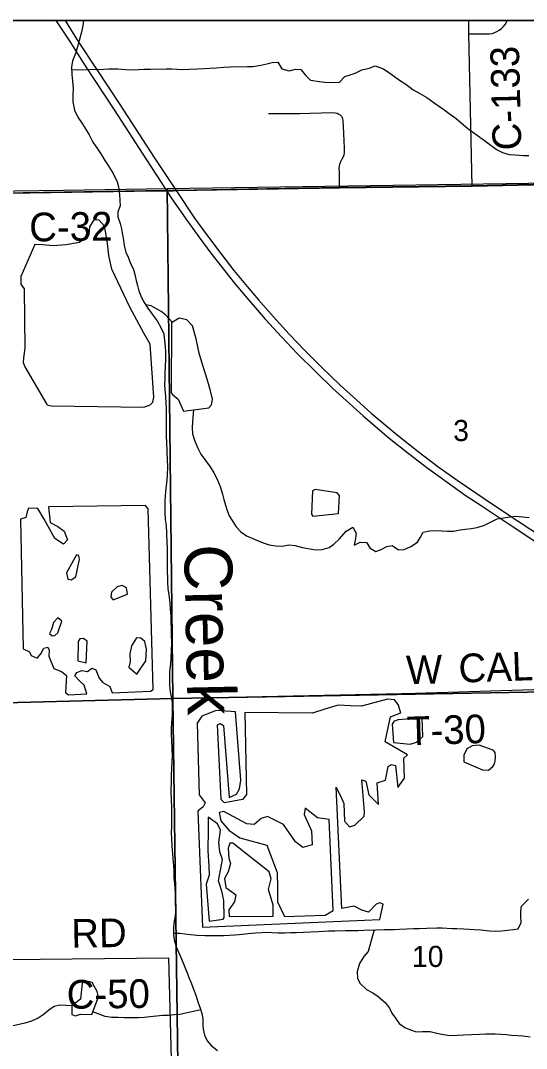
# Model space of a CAD drawing. Extents: x 0 to 36.9, y 0 to 22.
# Drawn here: x 6.858 to 7.859, y 18.864 to 20.9 of the extents above; entities that cross this region are included whole.
import ezdxf

# ---------------------------------------------------------------- set-up
doc = ezdxf.new("R2010")
doc.units = 0
for name, color, linetype in [('GM_X_County_Road', 7, 'Continuous'), ('GM_X_County_Road_Text', 7, 'Continuous'), ('GM_X_Interstate_Route', 7, 'Continuous'), ('GM_X_Major_River', 7, 'Continuous'), ('GM_X_Major_River_Text', 7, 'Continuous'), ('GM_X_Minor_Lake', 7, 'Continuous'), ('GM_X_Minor_River', 7, 'Continuous'), ('GM_X_Rail_Line', 7, 'Continuous'), ('GM_X_Section', 7, 'Continuous'), ('GM_X_Section_Text', 7, 'Continuous'), ('GM_X_Township_Road', 7, 'Continuous'), ('GM_X_Township_Road_Text', 7, 'Continuous'), ('SH_Cut_Line', 7, 'Continuous'), ('SH_Data', 7, 'Continuous')]:
    doc.layers.add(name, color=color, linetype=linetype)

msp = doc.modelspace()

# ---------------------------------------------------------------- linework, layer by layer
at = {"layer": 'GM_X_County_Road'}
for p, q in [((7.1241, 20.5624), (7.141, 20.5627)), ((7.1903, 17.5251), (7.1513, 19.0425))]:
    msp.add_line(p, q, dxfattribs=at)
for points in [[(7.7516, 20.5719), (7.7455, 20.8734), (7.745, 20.9)], [(7.1599, 20.563), (7.1658, 20.5631), (7.4891, 20.5688), (7.7516, 20.5719)], [(7.7516, 20.5719), (8.1453, 20.5805), (8.4791, 20.5838)], [(6.1629, 20.5471), (6.1729, 20.5473), (7.1241, 20.5624)], [(7.141, 20.5627), (7.147, 20.5628), (7.1599, 20.563)], [(7.1513, 19.0425), (6.3225, 19.0341), (5.5744, 19.0226)]]:
    msp.add_lwpolyline(points, dxfattribs=at)
at = {"layer": 'GM_X_Interstate_Route'}
for points in [[(6.9276, 20.9), (6.955, 20.8582), (6.9859, 20.8105), (7.043, 20.7231), (7.1073, 20.6241), (7.1371, 20.5785), (7.147, 20.5628), (7.1487, 20.5602)], [(6.9458, 20.9), (6.9706, 20.8604), (7.0082, 20.804), (7.054, 20.7339), (7.1224, 20.6287), (7.1658, 20.5631)], [(7.1487, 20.5602), (7.1557, 20.5489), (7.185, 20.5072), (7.2106, 20.4716), (7.2347, 20.4391), (7.2567, 20.4109), (7.2809, 20.3805), (7.3094, 20.3463), (7.3426, 20.3081), (7.3741, 20.2735), (7.4057, 20.2402), (7.4428, 20.2033), (7.4757, 20.1713), (7.5023, 20.1471), (7.5362, 20.1167), (7.5876, 20.0729), (7.6281, 20.0409), (7.6647, 20.0124), (7.7026, 19.9854), (7.7381, 19.9599), (7.7694, 19.9392), (7.8251, 19.9023), (7.8759, 19.8687)], [(7.1658, 20.5631), (7.2018, 20.5089), (7.2259, 20.4763), (7.2543, 20.4387), (7.2801, 20.4051), (7.3063, 20.3732), (7.329, 20.3467), (7.3588, 20.3133), (7.3894, 20.2789), (7.4211, 20.246), (7.4535, 20.2135), (7.4905, 20.1778), (7.5234, 20.1482), (7.5522, 20.1225), (7.6035, 20.0797), (7.6447, 20.0464), (7.684, 20.0167), (7.722, 19.9893), (7.759, 19.9643), (7.7901, 19.9432), (7.8431, 19.9082), (7.8929, 19.8754)]]:
    msp.add_lwpolyline(points, dxfattribs=at)
at = {"layer": 'GM_X_Major_River'}
for points in [[(6.9824, 20.9), (6.9811, 20.89), (6.9787, 20.8767), (6.974, 20.8607), (6.9708, 20.8477), (6.9661, 20.8328), (6.9603, 20.8202), (6.9586, 20.8076), (6.9593, 20.7932), (6.9606, 20.7799), (6.9617, 20.7652), (6.9615, 20.7534), (6.961, 20.739), (6.9643, 20.7223), (6.9714, 20.7088), (6.9796, 20.696), (6.9866, 20.6855), (6.9933, 20.6735), (7.0011, 20.6592), (7.0101, 20.6457), (7.0183, 20.6341), (7.0246, 20.6225), (7.0312, 20.6127), (7.0414, 20.5969), (7.0489, 20.5808), (7.0517, 20.5706), (7.0539, 20.5554), (7.0541, 20.5433), (7.0547, 20.5327), (7.0503, 20.5212), (7.0505, 20.5109), (7.0549, 20.4977), (7.0574, 20.4872), (7.0595, 20.4758), (7.0616, 20.4648), (7.0629, 20.4546), (7.0662, 20.4414), (7.0705, 20.4312), (7.0757, 20.4188), (7.0808, 20.4086), (7.084, 20.3969), (7.0865, 20.3848), (7.089, 20.375), (7.0918, 20.3648), (7.0958, 20.355), (7.1009, 20.3437), (7.1095, 20.3302), (7.1181, 20.3182), (7.1282, 20.3051), (7.1357, 20.2923), (7.1412, 20.2792), (7.143, 20.2655), (7.1439, 20.2538), (7.1445, 20.2435), (7.1447, 20.2303), (7.1439, 20.2135), (7.1433, 20.2018), (7.1432, 20.1911), (7.143, 20.1794)], [(7.143, 20.1794), (7.1435, 20.1691), (7.1449, 20.1555), (7.1455, 20.1422), (7.1457, 20.1308), (7.1461, 20.1134), (7.1459, 20.0986), (7.1458, 20.0868), (7.146, 20.0762), (7.1465, 20.0648), (7.1472, 20.0473), (7.1479, 20.0291), (7.1485, 20.0174), (7.1481, 19.9991), (7.1469, 19.9836), (7.1451, 19.974), (7.1439, 19.9588), (7.1437, 19.9478), (7.1435, 19.9357), (7.1433, 19.9254), (7.1443, 19.9114), (7.1457, 19.9), (7.1467, 19.8845), (7.1474, 19.8659), (7.148, 19.8564), (7.1482, 19.8416), (7.1481, 19.8302), (7.1479, 19.8166), (7.1484, 19.7881), (7.1494, 19.7741), (7.1512, 19.7631), (7.153, 19.746), (7.1539, 19.735), (7.1553, 19.7203), (7.156, 19.6831), (7.1567, 19.6679), (7.1562, 19.652), (7.1553, 19.6371), (7.1544, 19.6261), (7.1527, 19.6105), (7.1526, 19.5946), (7.1525, 19.5836), (7.1538, 19.5703), (7.1559, 19.5605), (7.158, 19.5495), (7.1582, 19.537), (7.1577, 19.5241), (7.1565, 19.5089), (7.1559, 19.4975), (7.1561, 19.4857), (7.1567, 19.4747), (7.1574, 19.4565), (7.1576, 19.444), (7.1571, 19.4322), (7.1565, 19.4193), (7.156, 19.4037), (7.1559, 19.3904), (7.1554, 19.3748), (7.1558, 19.3555), (7.1564, 19.3422), (7.1566, 19.3312), (7.1568, 19.3183), (7.1563, 19.3042), (7.1562, 19.2906), (7.1563, 19.2807), (7.157, 19.2644), (7.1584, 19.2504), (7.159, 19.2394), (7.1603, 19.2265), (7.1609, 19.2147), (7.1615, 19.2022), (7.1625, 19.1901), (7.164, 19.1723), (7.1645, 19.162), (7.1649, 19.1389), (7.164, 19.1263), (7.1612, 19.1123), (7.1603, 19.1027), (7.1605, 19.0876), (7.1626, 19.0762), (7.1663, 19.0638), (7.1714, 19.0532), (7.1773, 19.0397), (7.1877, 19.014), (7.1909, 19.0042), (7.1956, 18.9941), (7.2004, 18.9816), (7.2048, 18.9692), (7.2088, 18.9563), (7.2136, 18.9435), (7.2165, 18.9329), (7.2186, 18.9223), (7.2188, 18.9113), (7.2193, 18.9019), (7.2218, 18.8901), (7.2273, 18.8792), (7.2351, 18.8695), (7.2474, 18.8599)]]:
    msp.add_lwpolyline(points, dxfattribs=at)
at = {"layer": 'GM_X_Minor_Lake'}
for points in [[(7.1142, 20.259), (7.1017, 20.2808), (7.0742, 20.3324), (7.0384, 20.4077), (7.0326, 20.4346), (7.0295, 20.4645), (7.0237, 20.4925), (7.0136, 20.5045), (7.003, 20.5055), (6.9945, 20.4913), (6.9932, 20.4753), (6.9744, 20.4606), (6.9471, 20.4559), (6.9232, 20.454), (6.9011, 20.4559), (6.8863, 20.4564), (6.858, 20.3933), (6.8583, 20.3777), (6.8652, 20.3687), (6.8664, 20.251), (6.8637, 20.2316), (6.8627, 20.2225), (6.8662, 20.2142), (6.9092, 20.1405), (6.9119, 20.1383), (6.9192, 20.1369), (7.1018, 20.1343), (7.1142, 20.139), (7.1198, 20.1444), (7.1216, 20.154)], [(7.2303, 20.133), (7.2359, 20.1388), (7.2376, 20.1499), (7.2339, 20.1665), (7.2271, 20.1896), (7.2183, 20.2164), (7.2111, 20.2409), (7.2053, 20.2697), (7.198, 20.2954), (7.1868, 20.307), (7.1719, 20.3105), (7.1569, 20.3011), (7.1557, 20.1625), (7.1595, 20.1588), (7.1699, 20.1502), (7.1806, 20.1261)], [(7.1216, 20.154), (7.1142, 20.259)], [(7.1806, 20.1261), (7.2303, 20.133)], [(7.489, 19.9593), (7.4844, 19.9642), (7.4409, 19.9714), (7.436, 19.9687), (7.4337, 19.9223), (7.4361, 19.9186), (7.4873, 19.9236)], [(7.4873, 19.9236), (7.489, 19.9593)], [(7.1103, 19.9331), (7.1049, 19.9395), (6.9129, 19.937), (6.9161, 19.9056), (6.9314, 19.8975), (6.9441, 19.8886), (6.9505, 19.8712), (6.943, 19.8627), (6.9253, 19.8742), (6.9045, 19.9122), (6.8917, 19.9336), (6.8734, 19.9341), (6.8705, 19.9268), (6.868, 19.9158), (6.8578, 19.9125), (6.8631, 19.6552), (6.8753, 19.6497), (6.8785, 19.6425), (6.8904, 19.637), (6.8982, 19.6459), (6.9041, 19.657), (6.9117, 19.6587), (6.9144, 19.653), (6.9135, 19.6412), (6.9238, 19.6167), (6.9391, 19.6105), (6.9487, 19.6027), (6.9466, 19.5693), (6.9524, 19.5644), (6.9888, 19.5666), (6.984, 19.5836), (6.9744, 19.5918), (6.9654, 19.6019), (6.9691, 19.6088), (6.979, 19.6123), (6.9904, 19.6103), (6.9987, 19.6172), (7.0067, 19.6136), (7.0131, 19.5974), (7.0204, 19.5887), (7.0346, 19.5806), (7.039, 19.5682), (7.115, 19.5714), (7.1206, 19.5752)], [(7.1206, 19.5752), (7.1103, 19.9331)], [(6.9485, 19.8062), (6.9513, 19.7934), (6.9582, 19.7924), (6.9672, 19.7982), (6.9701, 19.8104), (6.9718, 19.8203), (6.9747, 19.8325), (6.9734, 19.8401), (6.9684, 19.8419)], [(6.9684, 19.8419), (6.9485, 19.8062)], [(7.0697, 19.7635), (7.0672, 19.776), (7.0592, 19.7808), (7.0493, 19.778), (7.0381, 19.7675), (7.0363, 19.758), (7.0414, 19.7528)], [(7.0414, 19.7528), (7.0697, 19.7635)], [(6.9397, 19.7104), (6.9317, 19.7167), (6.9231, 19.7075), (6.9187, 19.6941), (6.915, 19.6861), (6.9201, 19.6812), (6.9257, 19.6821), (6.9314, 19.6871)], [(6.9314, 19.6871), (6.9397, 19.7104)], [(6.9898, 19.671), (6.9825, 19.6762), (6.9749, 19.6753), (6.972, 19.6699), (6.9711, 19.6316), (6.9875, 19.6277)], [(6.9875, 19.6277), (6.9898, 19.671)], [(7.1057, 19.6316), (7.1068, 19.6551), (7.1035, 19.6699), (7.0962, 19.6766), (7.0874, 19.6772), (7.0774, 19.6615), (7.0743, 19.6455), (7.0749, 19.6303), (7.072, 19.6192), (7.0882, 19.6051)], [(7.0882, 19.6051), (7.1057, 19.6316)], [(7.218, 19.1041), (7.5691, 19.1195), (7.5758, 19.15), (7.5689, 19.1526), (7.5618, 19.1498), (7.5464, 19.134), (7.5334, 19.1379), (7.5181, 19.1456), (7.4938, 19.1414), (7.4827, 19.3816), (7.4941, 19.3586), (7.4977, 19.3488), (7.4994, 19.3143), (7.5091, 19.3031), (7.5193, 19.3063), (7.538, 19.3241), (7.539, 19.3328), (7.5335, 19.3958), (7.5411, 19.3932), (7.5476, 19.366), (7.5662, 19.347), (7.564, 19.3902), (7.5806, 19.3954), (7.5859, 19.4221), (7.5915, 19.4264), (7.6003, 19.4246), (7.6048, 19.381), (7.6182, 19.3991), (7.6168, 19.4389), (7.6239, 19.4455), (7.5794, 19.471), (7.5904, 19.5209), (7.6108, 19.5285), (7.6052, 19.5451), (7.5982, 19.5545), (7.5841, 19.5561), (7.533, 19.542), (7.5109, 19.5427), (7.4866, 19.5438), (7.4605, 19.5362), (7.4355, 19.5278), (7.3016, 19.5293), (7.305, 19.3669), (7.2972, 19.3572), (7.2612, 19.3505), (7.255, 19.3573), (7.2476, 19.5052), (7.2529, 19.5076), (7.2598, 19.5039), (7.2709, 19.3613), (7.2856, 19.3677), (7.2915, 19.3784), (7.2939, 19.3951), (7.283, 19.5309), (7.2449, 19.5333), (7.2169, 19.5222), (7.2077, 19.5084), (7.2111, 19.366), (7.2235, 19.3503), (7.2195, 19.3422), (7.209, 19.3337)], [(7.6528, 19.5185), (7.6053, 19.5151), (7.5974, 19.5119), (7.5937, 19.5065), (7.5962, 19.4701), (7.6289, 19.4669), (7.6418, 19.4709), (7.6545, 19.4817)], [(7.6545, 19.4817), (7.6528, 19.5185)], [(7.7918, 19.4556), (7.7658, 19.465), (7.7518, 19.4632), (7.7412, 19.4577), (7.7353, 19.4451), (7.7356, 19.4314), (7.7723, 19.4161), (7.7845, 19.4152), (7.7931, 19.4222)], [(7.7979, 19.4413), (7.7977, 19.4504), (7.7942, 19.4539), (7.7918, 19.4556)], [(7.7931, 19.4222), (7.7961, 19.4275), (7.7973, 19.4327), (7.7979, 19.4413)], [(7.209, 19.3337), (7.218, 19.1041)], [(7.2607, 19.1231), (7.2601, 19.1569), (7.2564, 19.1754), (7.2496, 19.1962), (7.2573, 19.2385), (7.2525, 19.2532), (7.2503, 19.2718), (7.2537, 19.2961), (7.2478, 19.3089), (7.2289, 19.3223), (7.2293, 19.2976), (7.2285, 19.2554), (7.2305, 19.2247), (7.2312, 19.2073), (7.225, 19.1893), (7.2311, 19.1161)], [(7.4686, 19.3172), (7.4457, 19.321), (7.4211, 19.3396), (7.419, 19.3274), (7.4339, 19.295), (7.4348, 19.2673), (7.4166, 19.262), (7.402, 19.2732), (7.3786, 19.3073), (7.3464, 19.3235), (7.3343, 19.3191), (7.3204, 19.3075), (7.3056, 19.3091), (7.2599, 19.3334), (7.2508, 19.331), (7.2545, 19.3147), (7.2704, 19.296), (7.2919, 19.2812), (7.3454, 19.2669), (7.3661, 19.2122), (7.3666, 19.1814), (7.3662, 19.1545), (7.38, 19.1255), (7.4606, 19.128), (7.4768, 19.137)], [(7.4768, 19.137), (7.4686, 19.3172)], [(7.3579, 19.1262), (7.3576, 19.1475), (7.3487, 19.1785), (7.3537, 19.1998), (7.3501, 19.2138), (7.278, 19.2707), (7.2723, 19.2706), (7.2687, 19.2607), (7.2698, 19.2406), (7.2734, 19.23), (7.2687, 19.2136), (7.2617, 19.2006), (7.2643, 19.1828), (7.2762, 19.1742), (7.2839, 19.1683), (7.2814, 19.1542), (7.2699, 19.1384), (7.2705, 19.1251)], [(7.2311, 19.1161), (7.2588, 19.1201)], [(7.2588, 19.1201), (7.2607, 19.1231)], [(7.2705, 19.1251), (7.3579, 19.1262)], [(7.0122, 18.9662), (7.0094, 18.9768), (6.9992, 18.9945), (6.9889, 18.9974), (6.9798, 18.993), (6.9762, 18.9615), (6.9593, 18.9483), (6.9595, 18.9312), (6.9668, 18.9286), (6.9763, 18.9318), (6.9991, 18.9311)], [(6.9991, 18.9311), (7.0122, 18.9662)]]:
    msp.add_lwpolyline(points, dxfattribs=at)
at = {"layer": 'GM_X_Minor_River'}
for points in [[(6.9589, 20.8021), (6.9929, 20.8033), (7.0229, 20.8039), (7.0327, 20.8044), (7.0506, 20.8044), (7.0658, 20.8031), (7.078, 20.8026), (7.0912, 20.8029), (7.1019, 20.8034), (7.1148, 20.804), (7.1459, 20.8046), (7.1573, 20.8041), (7.1676, 20.8039), (7.1793, 20.8033), (7.1922, 20.804), (7.2082, 20.8043), (7.2219, 20.8049), (7.2325, 20.8055), (7.245, 20.8065), (7.2605, 20.8075), (7.2734, 20.8081), (7.3072, 20.8087), (7.3179, 20.8093), (7.3334, 20.8115), (7.3451, 20.8144), (7.3557, 20.8169), (7.3671, 20.8174), (7.3753, 20.8043), (7.3898, 20.8004), (7.4019, 20.8037), (7.4129, 20.8031), (7.4211, 20.7926), (7.4315, 20.7822), (7.4494, 20.7791), (7.4601, 20.7778), (7.4749, 20.7773), (7.4889, 20.7779), (7.5001, 20.7891), (7.5103, 20.7927), (7.5201, 20.7956), (7.5333, 20.8023), (7.5477, 20.806), (7.5601, 20.81), (7.5762, 20.8046), (7.5908, 20.7942), (7.6077, 20.7816), (7.6204, 20.7739), (7.6354, 20.7628), (7.6485, 20.7558), (7.6619, 20.7477), (7.6769, 20.7369), (7.6957, 20.724), (7.7061, 20.7162), (7.7204, 20.7062), (7.73, 20.6977), (7.7431, 20.6861), (7.7762, 20.6625), (7.7893, 20.6528), (7.8012, 20.6439), (7.8119, 20.6388), (7.8253, 20.6349), (7.8371, 20.6343), (7.8531, 20.6327), (7.8641, 20.6325)], [(7.121, 20.3324), (7.1161, 20.3346), (7.1054, 20.3367)], [(7.1585, 20.3021), (7.1448, 20.3169), (7.1363, 20.3236), (7.121, 20.3324)], [(7.2002, 20.1288), (7.1982, 20.106), (7.1973, 20.0931), (7.1983, 20.0817), (7.2019, 20.0688), (7.2079, 20.0541), (7.2149, 20.041), (7.2239, 20.0283), (7.2329, 20.0159), (7.2407, 20.0039), (7.2462, 19.9926), (7.2529, 19.9768), (7.2574, 19.9621), (7.2602, 19.9511), (7.2635, 19.9398), (7.2667, 19.9296), (7.271, 19.919), (7.2777, 19.9074), (7.2847, 19.8969), (7.294, 19.8872), (7.3052, 19.879), (7.3178, 19.874), (7.3285, 19.8692), (7.34, 19.8649), (7.3499, 19.8616), (7.3629, 19.8596), (7.3762, 19.8587), (7.3887, 19.8612), (7.4016, 19.8599), (7.4161, 19.8564), (7.4275, 19.8543), (7.442, 19.8519), (7.4549, 19.8522), (7.4685, 19.8562), (7.4783, 19.8625), (7.4891, 19.8733), (7.5021, 19.8883), (7.5153, 19.8962), (7.5223, 19.8849), (7.521, 19.8739), (7.5182, 19.8609), (7.5302, 19.8668), (7.5428, 19.8659), (7.5502, 19.8551), (7.5613, 19.8484), (7.5715, 19.8524), (7.5828, 19.8579), (7.5938, 19.8604), (7.6061, 19.8515), (7.6174, 19.8521), (7.6306, 19.858), (7.6434, 19.867), (7.6497, 19.877), (7.6548, 19.8866), (7.6684, 19.8895), (7.679, 19.8901), (7.6916, 19.8895), (7.703, 19.8886), (7.7148, 19.8888), (7.728, 19.8909), (7.739, 19.8927), (7.75, 19.894), (7.7621, 19.8961), (7.7761, 19.9002), (7.7892, 19.9072), (7.8017, 19.9128), (7.8142, 19.9153), (7.827, 19.917), (7.8377, 19.918), (7.8521, 19.9171), (7.865, 19.9158)], [(7.1605, 19.0925), (7.173, 19.092), (7.1829, 19.091), (7.1939, 19.0897), (7.2065, 19.0884), (7.2224, 19.0876), (7.2342, 19.0874), (7.2604, 19.0879), (7.271, 19.0884), (7.2813, 19.089), (7.2908, 19.0899), (7.3086, 19.0914), (7.3226, 19.0928), (7.3363, 19.0938), (7.3458, 19.094), (7.3553, 19.0934), (7.3678, 19.0932), (7.3811, 19.0931), (7.3921, 19.0933), (7.4042, 19.0939), (7.4179, 19.0942), (7.4316, 19.0948), (7.4479, 19.0958), (7.4676, 19.0966), (7.4797, 19.0972), (7.5014, 19.0976), (7.5139, 19.0974), (7.5253, 19.0976), (7.5371, 19.0982), (7.561, 19.0987), (7.5784, 19.0994), (7.5982, 19.0997), (7.608, 19.1003), (7.6228, 19.1009), (7.6357, 19.1015), (7.6468, 19.1017), (7.6623, 19.1024), (7.6821, 19.1028), (7.6927, 19.1026), (7.7117, 19.1018), (7.7216, 19.1012), (7.7356, 19.1007), (7.7459, 19.1005), (7.7558, 19.0995), (7.7691, 19.0986), (7.7862, 19.0971), (7.7984, 19.0965), (7.8101, 19.0971), (7.8219, 19.0981), (7.8332, 19.0994), (7.8431, 19.1011), (7.8486, 19.1134), (7.8484, 19.1255), (7.8485, 19.1361), (7.8499, 19.1457), (7.8637, 19.1596)], [(7.5576, 19.0986), (7.5458, 19.0559), (7.5372, 19.0462), (7.5291, 19.032), (7.5241, 19.0164), (7.5247, 19.0027), (7.5302, 18.9926), (7.543, 18.981), (7.5549, 18.974), (7.5656, 18.967), (7.5803, 18.9544), (7.5884, 18.9439), (7.5928, 18.9337), (7.5998, 18.9236), (7.6076, 18.9131), (7.6187, 18.9053), (7.6295, 18.9006), (7.6413, 18.897), (7.6538, 18.8976), (7.669, 18.8975), (7.682, 18.8943), (7.6953, 18.8915), (7.7082, 18.8899), (7.7223, 18.8901), (7.7348, 18.8907), (7.7504, 18.8918), (7.7663, 18.8924), (7.7792, 18.8927), (7.7974, 18.8926), (7.8085, 18.8921), (7.8199, 18.8915), (7.8294, 18.8905), (7.8423, 18.8896), (7.8522, 18.8891), (7.8667, 18.887)], [(6.9595, 18.9484), (6.9352, 18.9495), (6.9246, 18.947), (6.9137, 18.94), (6.9028, 18.9303), (6.8923, 18.9236), (6.8795, 18.9181), (6.8663, 18.9137), (6.8493, 18.9099), (6.8387, 18.9079), (6.8285, 18.9061), (6.8171, 18.904), (6.8062, 18.9), (6.7931, 18.8888), (6.7857, 18.8788), (6.7783, 18.8677), (6.7682, 18.8561), (6.7555, 18.8441)], [(7.2146, 18.9401), (7.1732, 18.931), (7.1622, 18.9308), (7.1505, 18.9295), (7.1391, 18.9289), (7.1205, 18.927), (7.1027, 18.9252), (7.0909, 18.9246), (7.0769, 18.9243), (7.0636, 18.9245), (7.0507, 18.9254), (7.0385, 18.9255), (7.0252, 18.9272), (7.0011, 18.9364)]]:
    msp.add_lwpolyline(points, dxfattribs=at)
at = {"layer": 'GM_X_Rail_Line'}
msp.add_lwpolyline([(8.9, 20.5927), (8.9, 20.9), (5.9205, 20.9), (5.9236, 20.5446), (6.1727, 20.5478), (7.1468, 20.5633), (7.1656, 20.5637), (7.4889, 20.5693), (7.7514, 20.5725), (8.1451, 20.581), (8.4706, 20.5777), (8.4791, 20.5781), (8.7004, 20.5894)], close=True, dxfattribs=at)
msp.add_lwpolyline([(8.9, 14.5158), (8.9, 20.5927), (8.7004, 20.5894), (8.4791, 20.5781), (8.4706, 20.5777), (8.1451, 20.581), (7.7514, 20.5725), (7.4889, 20.5693), (7.1656, 20.5637), (7.1468, 20.5633), (6.1727, 20.5478), (5.9236, 20.5446), (5.3186, 20.5329), (5.2978, 20.5324), (5.1496, 20.5295), (4.5929, 20.5183), (4.1742, 20.5119), (4.2095, 19.5156), (4.2124, 19.4314), (4.22, 18.531), (4.2174, 18.4382), (4.2214, 17.442), (4.2237, 16.806), (4.2428, 16.065)], dxfattribs=at)
at = {"layer": 'GM_X_Section'}
for points in [[(7.1483, 20.5676), (7.1591, 19.5574), (6.1867, 19.5319), (6.1696, 20.5537), (6.9427, 20.5639)], [(8.1429, 20.5815), (8.157, 19.5752), (7.1591, 19.5574), (7.1483, 20.5676), (7.9531, 20.5791)], [(8.157, 19.5752), (8.1724, 18.5598), (7.173, 18.5435), (7.1591, 19.5574)], [(7.1591, 19.5574), (7.173, 18.5435), (6.2072, 18.5313), (6.1867, 19.5319)]]:
    msp.add_lwpolyline(points, close=True, dxfattribs=at)
at = {"layer": 'GM_X_Township_Road'}
for points in [[(7.7455, 20.8734), (7.786, 20.8739), (7.7915, 20.8746), (7.7965, 20.8763), (7.8009, 20.8784), (7.8056, 20.8811), (7.8099, 20.8843), (7.8141, 20.8881), (7.8172, 20.8924), (7.8199, 20.8965), (7.8214, 20.9)], [(7.4891, 20.5688), (7.489, 20.6006), (7.4887, 20.6071), (7.4889, 20.6114), (7.4898, 20.6157), (7.492, 20.6209), (7.4946, 20.6259), (7.4972, 20.6306), (7.4982, 20.6338), (7.4991, 20.6382), (7.4991, 20.647), (7.4969, 20.6911), (7.4967, 20.701), (7.4957, 20.7062), (7.4939, 20.7097), (7.4913, 20.7124), (7.4881, 20.714), (7.4849, 20.7157), (7.4816, 20.7168), (7.4743, 20.717), (7.4101, 20.7154), (7.3484, 20.715)], [(7.1087, 19.5562), (7.1211, 19.5565), (7.6128, 19.567), (7.6186, 19.5672)], [(7.6186, 19.5672), (7.8942, 19.5757), (8.1561, 19.5805)], [(6.5233, 19.5422), (6.5386, 19.5426), (6.8533, 19.55), (7.1087, 19.5562)]]:
    msp.add_lwpolyline(points, dxfattribs=at)
at = {"layer": 'SH_Cut_Line'}
msp.add_lwpolyline([(8.9, 14.5158), (8.9, 20.9), (2.1, 20.9), (2.1, 14.4405)], dxfattribs=at)
at = {"layer": 'SH_Data'}
msp.add_line((2.1, 20.9), (8.9, 20.9), dxfattribs=at)

# ---------------------------------------------------------------- texts
at = {"layer": 'GM_X_County_Road_Text'}
for s, rotation, p in [('C-133', 91.3773, (7.8494, 20.6435)), ('C-32', 0.6871, (6.8752, 20.4624)), ('RD', 0.9872, (6.9586, 19.0632)), ('C-50', 0.6858, (6.9494, 18.9424))]:
    msp.add_text(s, height=0.05682, rotation=rotation, dxfattribs=at).set_placement(p)
at = {"layer": 'GM_X_Major_River_Text'}
msp.add_text('Creek', height=0.09473, rotation=271.2261, dxfattribs=at).set_placement((7.1814, 19.8617))
at = {"layer": 'GM_X_Section_Text'}
for s, height, p in [('3', 0.0419, (7.7144, 20.067)), ('10', 0.04186, (7.6328, 19.0253))]:
    msp.add_text(s, height=height, rotation=0, dxfattribs=at).set_placement(p)
at = {"layer": 'GM_X_Township_Road_Text'}
for s, height, rotation, p in [('CALLA', 0.05682, 1.9891, (7.7258, 19.5884)), ('W', 0.0568, 1.4494, (7.6218, 19.5851)), ('T-30', 0.05682, 1.7682, (7.6237, 19.4642))]:
    msp.add_text(s, height=height, rotation=rotation, dxfattribs=at).set_placement(p)

doc.saveas('drawing.dxf')
